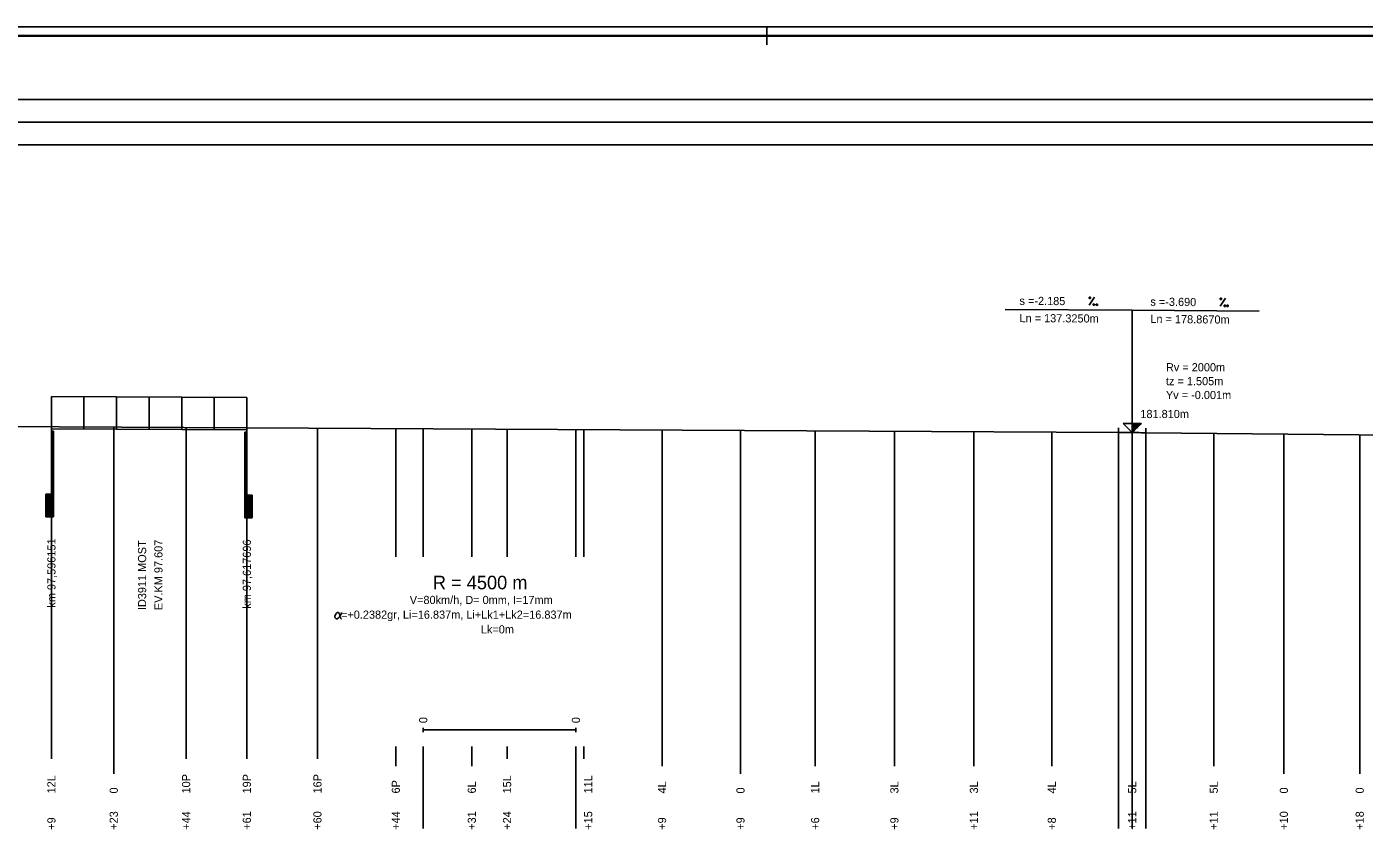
# Model space of a CAD drawing. Extents: x 0 to 10087, y -805 to 297.
# Drawn here: x 2566.9 to 2861.7, y 120.1 to 297 of the extents above; entities that cross this region are included whole.
import ezdxf

# ---------------------------------------------------------------- set-up
doc = ezdxf.new("R2010")
doc.units = 0
for name, color, linetype in [('CARKY_HODNOT', 7, 'Continuous'), ('NIVELETA_CARA', 7, 'Continuous'), ('NIVELETA_TEXT', 7, 'Continuous'), ('OBJEKTY_TEXT', 7, 'Continuous'), ('OBJEKTY_TVAR', 7, 'Continuous'), ('PARAM_R', 7, 'Continuous'), ('PARAM_TEXT', 7, 'Continuous'), ('PREV_CARA', 7, 'Continuous'), ('PREV_TEXT', 7, 'Continuous'), ('RAM', 7, 'Continuous'), ('TEXT', 7, 'Continuous')]:
    doc.layers.add(name, color=color, linetype=linetype)

msp = doc.modelspace()

# ---------------------------------------------------------------- linework, layer by layer
at = {"layer": 'CARKY_HODNOT'}
for p, q in [((2572.3, 138.35), (2572.3, 208.85)), ((2586.04, 138.35), (2586.04, 208.78)), ((2602, 138.35), (2602, 208.69)), ((2615.39, 138.35), (2615.39, 208.62)), ((2630.95, 138.35), (2630.95, 208.53)), ((2648.23, 180.14), (2648.23, 208.44)), ((2654.27, 180.14), (2654.27, 208.4)), ((2664.98, 180.14), (2664.98, 208.35)), ((2672.76, 180.14), (2672.76, 208.3)), ((2687.94, 180.14), (2687.94, 208.22)), ((2689.69, 180.14), (2689.69, 208.21)), ((2706.92, 138.35), (2706.92, 208.12)), ((2724.22, 138.35), (2724.22, 208.02)), ((2740.68, 138.35), (2740.68, 207.93)), ((2758.14, 138.35), (2758.14, 207.84)), ((2775.68, 138.35), (2775.68, 207.74)), ((2792.86, 138.35), (2792.86, 207.65)), ((2807.57, 138.35), (2807.57, 207.57)), ((2810.58, 138.35), (2810.58, 207.55)), ((2810.58, 138.35), (2810.58, 207.55)), ((2813.59, 138.35), (2813.59, 207.52)), ((2828.55, 138.35), (2828.55, 207.38)), ((2844.01, 138.35), (2844.01, 207.24)), ((2860.73, 138.35), (2860.73, 207.09)), ((2572.3, 135.65), (2572.3, 138.35)), ((2586.04, 132.35), (2586.04, 138.35)), ((2602, 135.65), (2602, 138.35)), ((2615.39, 135.65), (2615.39, 138.35)), ((2630.95, 135.65), (2630.95, 138.35)), ((2648.23, 134), (2648.23, 138.35)), ((2654.27, 126.2), (2654.27, 138.35)), ((2664.98, 134), (2664.98, 138.35)), ((2672.76, 135.65), (2672.76, 138.35)), ((2687.94, 126.2), (2687.94, 138.35)), ((2689.69, 135.65), (2689.69, 138.35)), ((2706.92, 134), (2706.92, 138.35)), ((2724.22, 132.35), (2724.22, 138.35)), ((2740.68, 134), (2740.68, 138.35)), ((2758.14, 134), (2758.14, 138.35)), ((2775.68, 134), (2775.68, 138.35)), ((2792.86, 134), (2792.86, 138.35)), ((2807.57, 126.2), (2807.57, 138.35)), ((2810.58, 134), (2810.58, 138.35)), ((2810.58, 126.2), (2810.58, 138.35)), ((2813.59, 126.2), (2813.59, 138.35)), ((2828.55, 134), (2828.55, 138.35)), ((2844.01, 132.35), (2844.01, 138.35)), ((2860.73, 132.35), (2860.73, 138.35)), ((2654.27, 120.25), (2654.27, 126.2)), ((2687.94, 120.25), (2687.94, 126.2)), ((2807.57, 120.25), (2807.57, 126.2)), ((2810.58, 120.25), (2810.58, 126.2)), ((2813.59, 120.25), (2813.59, 126.2))]:
    msp.add_line(p, q, dxfattribs=at)
at = {"layer": 'NIVELETA_CARA'}
for p, q in [((300, 281), (8321.33, 281)), ((300, 276), (8321.33, 276)), ((300, 271), (8321.33, 271)), ((2810.58, 234.55), (2782.58, 234.7)), ((2810.58, 207.55), (2810.58, 234.55)), ((2810.58, 234.55), (2838.58, 234.29)), ((2810.58, 207.55), (2808.58, 209.55)), ((2808.58, 209.55), (2812.58, 209.55)), ((2810.58, 207.55), (2810.58, 209.55)), ((2812.58, 209.55), (2810.58, 207.55)), ((2810.65, 207.62), (2810.65, 209.55)), ((2810.72, 207.68), (2810.72, 209.55)), ((2810.78, 207.75), (2810.78, 209.55)), ((2810.85, 207.82), (2810.85, 209.55)), ((2810.92, 207.88), (2810.92, 209.55)), ((2810.98, 207.95), (2810.98, 209.55)), ((2811.05, 208.02), (2811.05, 209.55)), ((2811.12, 208.08), (2811.12, 209.55)), ((2811.18, 208.15), (2811.18, 209.55)), ((2811.25, 208.22), (2811.25, 209.55)), ((2811.32, 208.28), (2811.32, 209.55)), ((2811.38, 208.35), (2811.38, 209.55)), ((2811.45, 208.42), (2811.45, 209.55)), ((2811.52, 208.48), (2811.52, 209.55)), ((2811.58, 208.55), (2811.58, 209.55)), ((2811.65, 208.62), (2811.65, 209.55)), ((2811.72, 208.68), (2811.72, 209.55)), ((2811.78, 208.75), (2811.78, 209.55)), ((2811.85, 208.82), (2811.85, 209.55)), ((2811.92, 208.88), (2811.92, 209.55)), ((2811.98, 208.95), (2811.98, 209.55)), ((2812.05, 209.02), (2812.05, 209.55)), ((2812.12, 209.08), (2812.12, 209.55)), ((2812.18, 209.15), (2812.18, 209.55)), ((2812.25, 209.22), (2812.25, 209.55)), ((2812.32, 209.28), (2812.32, 209.55)), ((2812.38, 209.35), (2812.38, 209.55)), ((2812.45, 209.42), (2812.45, 209.55)), ((2812.52, 209.48), (2812.52, 209.55)), ((2539.94, 209.03), (2807.57, 207.57)), ((2807.57, 207.57), (2807.57, 208.57)), ((2807.57, 207.57), (2810.58, 207.55)), ((2807.57, 207.57), (2808.07, 207.56)), ((2808.07, 207.56), (2808.57, 207.56)), ((2808.57, 207.56), (2809.07, 207.56)), ((2809.07, 207.56), (2809.57, 207.55)), ((2809.57, 207.55), (2810.07, 207.55)), ((2810.07, 207.55), (2810.57, 207.55)), ((2810.57, 207.55), (2810.58, 207.55)), ((2810.58, 207.55), (2813.59, 207.52)), ((2810.58, 207.55), (2811.08, 207.54)), ((2811.08, 207.54), (2811.58, 207.54)), ((2811.58, 207.54), (2812.08, 207.54)), ((2812.08, 207.54), (2812.58, 207.53)), ((2812.58, 207.53), (2813.08, 207.53)), ((2813.08, 207.53), (2813.58, 207.52)), ((2813.58, 207.52), (2813.59, 207.52)), ((2813.59, 207.52), (2813.59, 208.52)), ((2813.59, 207.52), (3161.05, 204.32))]:
    msp.add_line(p, q, dxfattribs=at)
at = {"layer": 'NIVELETA_TEXT'}
for p, q in [((2801.1, 237.4), (2801.09, 237.1)), ((2801.09, 235.61), (2802.29, 237.39)), ((2801.09, 237.1), (2801.39, 237.1)), ((2801.39, 237.4), (2801.1, 237.4)), ((2801.1, 237.4), (2801.1, 237.39)), ((2801.39, 237.1), (2801.39, 237.4)), ((2829.94, 235.38), (2831.14, 237.16)), ((2829.95, 237.17), (2829.95, 236.87)), ((2829.96, 237.17), (2829.95, 237.16)), ((2829.95, 236.87), (2830.25, 236.87)), ((2830.25, 237.17), (2829.96, 237.17)), ((2830.25, 236.87), (2830.25, 237.17)), ((2802, 235.9), (2802, 235.6)), ((2802.29, 235.89), (2802, 235.9)), ((2802, 235.9), (2802, 235.89)), ((2802, 235.6), (2802.29, 235.6)), ((2802.29, 235.6), (2802.29, 235.89)), ((2802.61, 235.89), (2802.61, 235.6)), ((2802.62, 235.89), (2802.61, 235.89)), ((2802.61, 235.6), (2802.91, 235.59)), ((2802.91, 235.89), (2802.62, 235.89)), ((2802.91, 235.59), (2802.91, 235.89)), ((2830.85, 235.66), (2830.84, 235.37)), ((2830.84, 235.37), (2831.14, 235.36)), ((2831.14, 235.66), (2830.85, 235.66)), ((2830.85, 235.66), (2830.85, 235.66)), ((2831.14, 235.36), (2831.14, 235.66)), ((2831.46, 235.66), (2831.46, 235.36)), ((2831.47, 235.66), (2831.46, 235.65)), ((2831.46, 235.36), (2831.76, 235.36)), ((2831.76, 235.65), (2831.47, 235.66)), ((2831.76, 235.36), (2831.76, 235.65))]:
    msp.add_line(p, q, dxfattribs=at)
at = {"layer": 'OBJEKTY_TVAR'}
for p, q in [((2572.3, 215.53), (2572.3, 208.35)), ((2572.3, 215.53), (2615.39, 215.3)), ((2579.48, 215.49), (2579.48, 208.31)), ((2586.67, 215.45), (2586.67, 208.27)), ((2593.85, 215.42), (2593.85, 208.23)), ((2601.03, 215.38), (2601.03, 208.19)), ((2608.21, 215.34), (2608.21, 208.16)), ((2615.39, 215.3), (2615.39, 208.12)), ((2572.3, 208.35), (2615.39, 208.12)), ((2572.3, 207.85), (2572.3, 193.99)), ((2572.3, 207.85), (2572.78, 207.85)), ((2572.4, 207.85), (2572.4, 193.99)), ((2572.5, 207.85), (2572.5, 193.99)), ((2572.54, 207.85), (2572.54, 193.99)), ((2572.6, 207.85), (2572.6, 193.99)), ((2572.7, 207.85), (2572.7, 193.99)), ((2572.78, 207.85), (2572.78, 193.99)), ((2614.91, 207.62), (2614.91, 193.75)), ((2614.91, 207.62), (2615.39, 207.62)), ((2615.01, 207.62), (2615.01, 193.75)), ((2615.11, 207.62), (2615.11, 193.75)), ((2615.15, 207.62), (2615.15, 193.75)), ((2615.21, 207.62), (2615.21, 193.75)), ((2615.31, 207.62), (2615.31, 193.75)), ((2615.39, 207.62), (2615.39, 193.75)), ((2571.1, 193.99), (2572.78, 193.99)), ((2571.1, 193.99), (2571.1, 188.96)), ((2571.1, 193.89), (2572.78, 193.89)), ((2571.1, 193.79), (2572.78, 193.79)), ((2571.1, 193.69), (2572.78, 193.69)), ((2571.1, 193.59), (2572.78, 193.59)), ((2571.1, 193.49), (2572.78, 193.49)), ((2571.1, 193.39), (2572.78, 193.39)), ((2571.1, 193.29), (2572.78, 193.29)), ((2571.1, 193.19), (2572.78, 193.19)), ((2571.1, 193.09), (2572.78, 193.09)), ((2571.1, 192.99), (2572.78, 192.99)), ((2571.1, 192.89), (2572.78, 192.89)), ((2571.1, 192.79), (2572.78, 192.79)), ((2571.1, 192.69), (2572.78, 192.69)), ((2571.1, 192.59), (2572.78, 192.59)), ((2571.1, 192.49), (2572.78, 192.49)), ((2571.1, 192.39), (2572.78, 192.39)), ((2571.1, 192.29), (2572.78, 192.29)), ((2571.1, 192.19), (2572.78, 192.19)), ((2571.1, 192.09), (2572.78, 192.09)), ((2571.1, 191.99), (2572.78, 191.99)), ((2571.1, 191.89), (2572.78, 191.89)), ((2571.1, 191.79), (2572.78, 191.79)), ((2571.1, 191.69), (2572.78, 191.69)), ((2572.78, 193.99), (2572.78, 188.96)), ((2614.91, 193.75), (2616.59, 193.75)), ((2614.91, 193.75), (2614.91, 188.73)), ((2614.91, 193.65), (2616.59, 193.65)), ((2614.91, 193.55), (2616.59, 193.55)), ((2614.91, 193.45), (2616.59, 193.45)), ((2614.91, 193.35), (2616.59, 193.35)), ((2614.91, 193.25), (2616.59, 193.25)), ((2614.91, 193.15), (2616.59, 193.15)), ((2614.91, 193.05), (2616.59, 193.05)), ((2614.91, 192.95), (2616.59, 192.95)), ((2614.91, 192.85), (2616.59, 192.85)), ((2614.91, 192.75), (2616.59, 192.75)), ((2614.91, 192.65), (2616.59, 192.65)), ((2614.91, 192.55), (2616.59, 192.55)), ((2614.91, 192.45), (2616.59, 192.45)), ((2614.91, 192.35), (2616.59, 192.35)), ((2614.91, 192.25), (2616.59, 192.25)), ((2614.91, 192.15), (2616.59, 192.15)), ((2614.91, 192.05), (2616.59, 192.05)), ((2614.91, 191.95), (2616.59, 191.95)), ((2614.91, 191.85), (2616.59, 191.85)), ((2614.91, 191.75), (2616.59, 191.75)), ((2616.59, 193.75), (2616.59, 188.73)), ((2571.1, 191.59), (2572.78, 191.59)), ((2571.1, 191.49), (2572.78, 191.49)), ((2571.1, 191.39), (2572.78, 191.39)), ((2571.1, 191.29), (2572.78, 191.29)), ((2571.1, 191.19), (2572.78, 191.19)), ((2571.1, 191.09), (2572.78, 191.09)), ((2571.1, 190.99), (2572.78, 190.99)), ((2571.1, 190.89), (2572.78, 190.89)), ((2571.1, 190.79), (2572.78, 190.79)), ((2571.1, 190.69), (2572.78, 190.69)), ((2571.1, 190.59), (2572.78, 190.59)), ((2571.1, 190.49), (2572.78, 190.49)), ((2571.1, 190.39), (2572.78, 190.39)), ((2571.1, 190.29), (2572.78, 190.29)), ((2571.1, 190.19), (2572.78, 190.19)), ((2571.1, 190.09), (2572.78, 190.09)), ((2571.1, 189.99), (2572.78, 189.99)), ((2571.1, 189.89), (2572.78, 189.89)), ((2571.1, 189.79), (2572.78, 189.79)), ((2571.1, 189.69), (2572.78, 189.69)), ((2571.1, 189.59), (2572.78, 189.59)), ((2571.1, 189.49), (2572.78, 189.49)), ((2571.1, 189.39), (2572.78, 189.39)), ((2571.1, 189.29), (2572.78, 189.29)), ((2571.1, 189.19), (2572.78, 189.19)), ((2571.1, 189.09), (2572.78, 189.09)), ((2571.1, 188.99), (2572.78, 188.99)), ((2571.1, 188.96), (2572.78, 188.96)), ((2614.91, 191.65), (2616.59, 191.65)), ((2614.91, 191.55), (2616.59, 191.55)), ((2614.91, 191.45), (2616.59, 191.45)), ((2614.91, 191.35), (2616.59, 191.35)), ((2614.91, 191.25), (2616.59, 191.25)), ((2614.91, 191.15), (2616.59, 191.15)), ((2614.91, 191.05), (2616.59, 191.05)), ((2614.91, 190.95), (2616.59, 190.95)), ((2614.91, 190.85), (2616.59, 190.85)), ((2614.91, 190.75), (2616.59, 190.75)), ((2614.91, 190.65), (2616.59, 190.65)), ((2614.91, 190.55), (2616.59, 190.55)), ((2614.91, 190.45), (2616.59, 190.45)), ((2614.91, 190.35), (2616.59, 190.35)), ((2614.91, 190.25), (2616.59, 190.25)), ((2614.91, 190.15), (2616.59, 190.15)), ((2614.91, 190.05), (2616.59, 190.05)), ((2614.91, 189.95), (2616.59, 189.95)), ((2614.91, 189.85), (2616.59, 189.85)), ((2614.91, 189.75), (2616.59, 189.75)), ((2614.91, 189.65), (2616.59, 189.65)), ((2614.91, 189.55), (2616.59, 189.55)), ((2614.91, 189.45), (2616.59, 189.45)), ((2614.91, 189.35), (2616.59, 189.35)), ((2614.91, 189.25), (2616.59, 189.25)), ((2614.91, 189.15), (2616.59, 189.15)), ((2614.91, 189.05), (2616.59, 189.05)), ((2614.91, 188.95), (2616.59, 188.95)), ((2614.91, 188.85), (2616.59, 188.85)), ((2614.91, 188.75), (2616.59, 188.75)), ((2614.91, 188.73), (2616.59, 188.73))]:
    msp.add_line(p, q, dxfattribs=at)
at = {"layer": 'PARAM_TEXT'}
for p, q in [((2634.81, 167.11), (2634.9, 167.39)), ((2634.81, 166.81), (2634.81, 167.11)), ((2634.9, 166.62), (2634.81, 166.81)), ((2634.9, 167.39), (2635, 167.59)), ((2635.1, 166.52), (2634.9, 166.62)), ((2635, 167.59), (2635.2, 167.79)), ((2635.3, 166.52), (2635.1, 166.52)), ((2635.2, 167.79), (2635.39, 167.88)), ((2635.49, 166.62), (2635.3, 166.52)), ((2635.39, 167.88), (2635.57, 167.89)), ((2635.79, 166.92), (2635.49, 166.62)), ((2635.57, 167.89), (2635.69, 167.78)), ((2635.69, 167.78), (2635.79, 167.59)), ((2635.79, 167.59), (2635.98, 166.81)), ((2635.98, 167.21), (2635.79, 166.92)), ((2636.08, 167.41), (2635.98, 167.21)), ((2635.98, 166.81), (2636.08, 166.62)), ((2636.18, 167.6), (2636.08, 167.41)), ((2636.08, 166.62), (2636.17, 166.52)), ((2636.17, 166.52), (2636.26, 166.52)), ((2636.27, 167.89), (2636.18, 167.6))]:
    msp.add_line(p, q, dxfattribs=at)
at = {"layer": 'PREV_CARA'}
msp.add_line((2654.27, 142), (2687.94, 142), dxfattribs=at)
at = {"layer": 'PREV_TEXT'}
for p, q in [((2654.27, 141.5), (2654.27, 142.5)), ((2687.94, 141.5), (2687.94, 142.5))]:
    msp.add_line(p, q, dxfattribs=at)
at = {"layer": 'RAM'}
for p, q in [((8636.33, 297), (0, 297)), ((8634.33, 295.1), (2, 295.1)), ((8634.33, 295), (2, 295)), ((8634.33, 294.9), (2, 294.9)), ((2730, 293), (2730, 297))]:
    msp.add_line(p, q, dxfattribs=at)

# ---------------------------------------------------------------- texts
at = {"layer": 'NIVELETA_TEXT'}
for s, rotation, p in [('s =-2.185', 359.6871, (2785.73, 235.69)), ('s =-3.690', 359.4715, (2814.58, 235.51)), ('Ln = 137.3250m', 359.6871, (2785.73, 231.89)), ('Ln = 178.8670m', 359.4715, (2814.58, 231.71))]:
    msp.add_text(s, height=1.8, rotation=rotation, dxfattribs=at).set_placement(p)
for s, p in [('Rv = 2000m', (2818.02, 221.05)), ('tz = 1.505m', (2818.02, 217.99)), ('Yv = -0.001m', (2818.02, 214.93)), ('181.810m', (2812.38, 210.75))]:
    msp.add_text(s, height=1.8, dxfattribs=at).set_placement(p)
at = {"layer": 'OBJEKTY_TEXT'}
for s, p in [('km 97,596151', (2573.2, 168.96)), ('ID3911 MOST ', (2593.19, 168.42)), ('EV.KM 97.607', (2596.79, 168.42)), ('km 97,617696', (2616.29, 168.73))]:
    msp.add_text(s, height=1.8, rotation=90, dxfattribs=at).set_placement(p)
at = {"layer": 'PARAM_R'}
msp.add_text('R = 4500 m', height=3, dxfattribs=at).set_placement((2656.4, 173))
at = {"layer": 'PARAM_TEXT'}
for s, p in [('V=80km/h, D= 0mm, I=17mm', (2651.31, 169.76)), ('  =+0.2382gr, Li=16.837m, Li+Lk1+Lk2=16.837m', (2634.81, 166.52)), ('Lk=0m', (2666.98, 163.28))]:
    msp.add_text(s, height=1.8, dxfattribs=at).set_placement(p)
at = {"layer": 'PREV_TEXT'}
for p in [(2655.17, 143.5), (2688.84, 143.5)]:
    msp.add_text('0', height=1.8, rotation=90, dxfattribs=at).set_placement(p)
at = {"layer": 'TEXT'}
for s, p in [('12L', (2573.2, 128)), ('10P', (2602.9, 128)), ('19P', (2616.29, 128)), ('16P', (2631.85, 128)), ('6P', (2649.13, 128)), ('6L', (2665.88, 128)), ('15L', (2673.66, 128)), ('11L', (2691.54, 128)), ('4L', (2707.82, 128)), ('1L', (2741.58, 128)), ('3L', (2759.04, 128)), ('3L', (2776.58, 128)), ('4L', (2793.76, 128)), ('5L', (2811.48, 128)), ('5L', (2829.45, 128)), ('0', (2586.94, 128)), ('0', (2725.12, 128)), ('0', (2844.91, 128)), ('0', (2861.63, 128)), ('+23', (2586.94, 120)), ('+44', (2602.9, 120)), ('+61', (2616.29, 120)), ('+60', (2631.85, 120)), ('+44', (2649.13, 120)), ('+31', (2665.88, 120)), ('+24', (2673.66, 120)), ('+15', (2691.54, 120)), ('+11', (2776.58, 120)), ('+11', (2811.48, 120)), ('+11', (2829.45, 120)), ('+10', (2844.91, 120)), ('+18', (2861.63, 120)), ('+9', (2573.2, 120)), ('+9', (2707.82, 120)), ('+9', (2725.12, 120)), ('+6', (2741.58, 120)), ('+9', (2759.04, 120)), ('+8', (2793.76, 120))]:
    msp.add_text(s, height=1.8, rotation=90, dxfattribs=at).set_placement(p)

doc.saveas('drawing.dxf')
